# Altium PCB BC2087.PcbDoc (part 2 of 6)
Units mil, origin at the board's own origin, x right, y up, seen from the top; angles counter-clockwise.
Board outline 7401.57 x 1181.1 mil, 6 copper layers (Top Copper, Signal Layer 1, Signal Layer 2, Signal Layer 3, Signal Layer 4, Bottom Copper), stack 62.874 mil thick; 302 components, 237 nets, 1184 pads, 867 vias.
Unrouted connection lines stored in the file: 315.
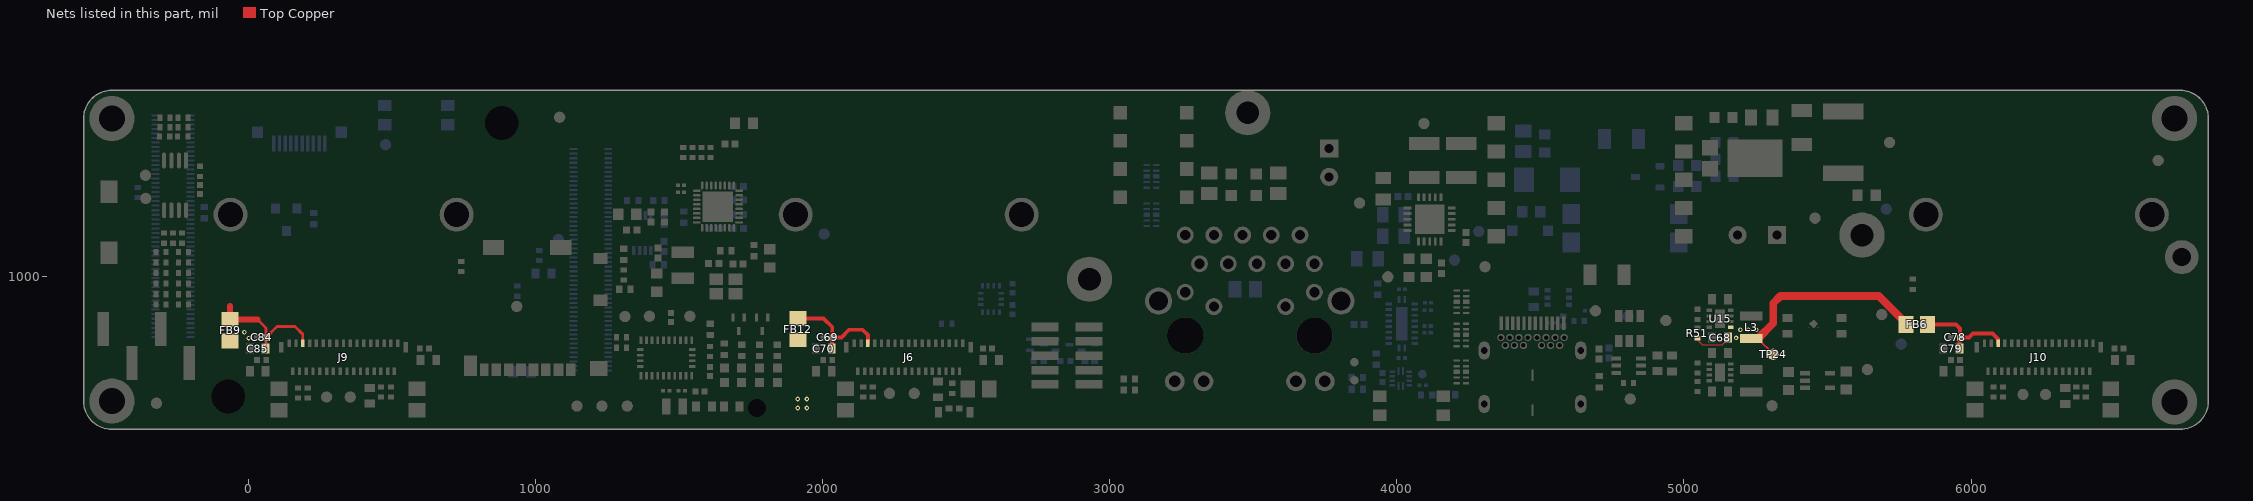
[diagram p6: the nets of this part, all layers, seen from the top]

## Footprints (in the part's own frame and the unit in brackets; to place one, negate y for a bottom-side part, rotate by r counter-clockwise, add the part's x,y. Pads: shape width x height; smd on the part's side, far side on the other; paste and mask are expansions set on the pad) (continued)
RESC0603(1608)_N [mm] "Chip Resistor, Body 1.6x0.8mm, IPC Medium Density"
  rect 0.9x1 smd: 1(-0.8,0) 2(0.8,0)
  silkscreen extent -0.05,-0.4 0.05,0.4, body extent -0.85,-0.47 0.85,0.47, height 0.6
RESC0805(2012)_N [mm] "Chip Resistor, Body 2.0x1.3mm, IPC Medium Density"
  rect 1.05x1.4 smd: 1(-0.95,0) 2(0.95,0)
  silkscreen extent -0.05,-0.6 0.05,0.6, body extent -1.1,-0.67 1.1,0.68, height 0.7
RESC1005X40X25NL05T05 [mm] "Chip Resistor, 2-Leads, Body 1.00x0.50mm, IPC Medium Density"
  rect 0.55x0.55 smd: 1(-0.45,0) 2(0.45,0)
  body extent -0.53,-0.27 0.53,0.28, height 0.4
RESC1005X40X25NL05T10 [mm] "Chip Resistor, 2-Leads, Body 1.00x0.50mm, IPC Medium Density"
  rect 0.6x0.55 smd: 1(-0.425,0) 2(0.425,0)
  body extent -0.53,-0.27 0.53,0.28, height 0.4
RS1B [mil] "Molded Diode, 2-Leads, Body 4.30x2.59mm, IPC Medium Density"
  rect 70x85 smd: 1(-80,0) 2(80,0)
  silkscreen extent -130,-59 91,59, body extent -102,-54 102,54, height 106
RTL8111Hx-CG [mm] "QFN, 32-Leads, Body 4.00x4.00mm, Pitch 0.40mm, Thermal Pad 2.70x2.70mm, IPC High Density"
  oval 0.7x0.2 smd mask+0.076: 1(-1.875,1.4) 2(-1.875,1) 3(-1.875,0.6) 4(-1.875,0.2) 5(-1.875,-0.2) 6(-1.875,-0.6) 7(-1.875,-1) 8(-1.875,-1.4) 17(1.875,-1.4) 18(1.875,-1) 19(1.875,-0.6) 20(1.875,-0.2) 21(1.875,0.2) 22(1.875,0.6) 23(1.875,1) 24(1.875,1.4)
  oval 0.2x0.7 smd mask+0.076: 9(-1.4,-1.875) 10(-1,-1.875) 11(-0.6,-1.875) 12(-0.2,-1.875) 13(0.2,-1.875) 14(0.6,-1.875) 15(1,-1.875) 16(1.4,-1.875) 25(1.4,1.875) 26(1,1.875) 27(0.6,1.875) 28(0.2,1.875) 29(-0.2,1.875) 30(-0.6,1.875) 31(-1,1.875) 32(-1.4,1.875)
  rect 2.7x2.7 smd paste-2 mask+0.076: 33(0,0)
  silkscreen extent -2.93,-2.15 2.15,2.15, body extent -2,-2 2,2, height 0.9
SFV10R-2STE1HLF [mm] "CONN FFC TOP 10POS 0.50MM R/A"
  rect 0.305x1.405 smd: 1(-2.258,0.494) 1(-2.258,0.494) 2(-1.759,0.494) 3(-1.258,0.494) 4(-0.758,0.494) 5(-0.258,0.494) 6(0.242,0.494) 7(0.741,0.494) 8(1.242,0.494) 9(1.742,0.494) 10(2.242,0.494)
  rect 1x1 smd: 11(-3.707,-0.486) 12(3.708,-0.494)
  Top Copper region: -3.958,0.394 -2.708,0.394 -2.708,-1.906 -3.958,-1.906
  Top Copper region: -5.358,-0.106 -2.708,-0.106 -2.708,-1.206 -5.358,-1.206
  Top Copper region: -4.658,0.394 -2.708,0.394 -2.708,-1.206 -4.658,-1.206
  Top Copper region: 4.642,-1.205 2.692,-1.205 2.692,0.395 4.642,0.395
  Top Copper region: 5.342,-1.205 2.692,-1.205 2.692,-0.105 5.342,-0.105
  Top Copper region: 3.942,-1.905 2.692,-1.905 2.692,0.395 3.942,0.395
  Keep-Out Layer region: 5.594,-5.708 5.594,-3.973 -5.611,-3.973 -5.611,-5.708
  body extent -5.26,-4.01 5.24,0.89, height 1.82
Si3404-A-GM [mm] "QFN, 20-Leads, Body 4.00x4.00mm, Pitch 0.50mm, Thermal Pad 2.60x2.60mm, IPC Medium Density"
  rect 0.7x0.25 smd: 1(-1.95,1) 2(-1.95,0.5) 3(-1.95,0) 4(-1.95,-0.5) 5(-1.95,-1) 11(1.95,-1) 12(1.95,-0.5) 13(1.95,0) 14(1.95,0.5) 15(1.95,1)
  rect 0.25x0.7 smd: 6(-1,-1.95) 7(-0.5,-1.95) 8(0,-1.95) 9(0.5,-1.95) 10(1,-1.95) 16(1,1.95) 17(0.5,1.95) 18(0,1.95) 19(-0.5,1.95) 20(-1,1.95)
  rect 2.6x2.6 smd paste-5: 21(0,0)
  silkscreen extent -2.82,-2.15 2.15,2.15, body extent -2,-2 2,2, height 0.9
SML_D1xx8W [mm] "Rohm LED SML_D1 series - Chip Diode, 2-Leads, Body 1.60x0.80mm, IPC High Density"
  rect 0.8x0.8 smd: 1(-0.625,0) 2(0.625,0)
  silkscreen extent -1.3,-0.5 -1.3,0.5, body extent -0.8,-0.4 0.8,0.4, height 0.6
TLV431BCDBZR [mm] "SOT-23-3"
  rrect18% 0.8x0.55 smd: 1(-1.1,0.95) 2(-1.1,-0.95) 3(1.1,0)
  silkscreen extent -1.23,-1.46 0.7,1.9, body extent -1.26,-1.46 1.26,1.46, height 0.96
TLV62080DSG [mm] "WSON-8, 2.1mm x 2.1mm x 0.8mm"
  rect 0.5x0.28 smd mask+0.07: 1(-0.95,0.75) 2(-0.95,0.25) 3(-0.95,-0.25) 4(-0.95,-0.75) 5(0.95,-0.75) 6(0.95,-0.25) 7(0.95,0.25) 8(0.95,0.75)
  rect 0.9x1.6 smd mask+0.07: 9(0,0)
  silkscreen extent -1.4,1.07 -1.35,1.13, body extent -1.05,-1.05 1.05,1.05, height 0.8
TLV70018DCK [mm] "SC70-5 1.1mm"
  rect 0.4x0.9 smd paste-0.025 mask+0.05: 1(-0.65,-1.1) 2(0,-1.1) 3(0.65,-1.1) 4(0.65,1.1) 5(-0.65,1.1)
  silkscreen extent -1.17,-1.63 -1.12,-1.57, body extent -1.1,-1.2 1.1,1.2, height 1.1
TP075_150_NS [mm] "0.75mm dia pad, 1.5mm dia clearance, no silk screen"
  round 0.75 smd paste-2: 1(0,0)
TP100_200_NS [mm] "1mm dia pad, 2mm dia clearance, no silk screen"
  round 1 smd paste-2: 1(0,0)
TPD4E02B04DQAR [mm] "TPD4E02B04DQAR"
  rrect50% 0.2x0.565 smd mask+0.07: 1(-1,-0.417) 2(-0.5,-0.417) 4(0.5,-0.417) 5(1,-0.417) 6(1,0.417) 7(0.5,0.417) 9(-0.5,0.417) 10(-1,0.417)
  rrect25% 0.4x0.565 smd mask+0.07: 3(0,-0.417) 8(0,0.417)
  silkscreen extent -1.4,-1.01 1.4,0.5, body extent -1.2,-0.71 1.2,0.71, height 0.55
TRJG0926HENL [mm] "TRXCOM TRJG0926HENL 1000BASE-T PoE"
  round 1.5 hole 0.9: 1(-5.715,8.89) 2(-4.445,6.35) 3(-3.175,8.89) 4(-1.905,6.35) 5(-0.635,8.89) 6(0.635,6.35) 7(1.905,8.89) 8(3.175,6.35) 9(4.445,8.89) 10(5.715,6.35) 11(-5.715,3.83) 12(-3.175,2.56) 13(3.175,2.56) 14(5.715,3.83)
  round 1.75 hole 1.02: 15(-6.63,-4.06) 16(-4.09,-4.06) 17(4.09,-4.06) 18(6.63,-4.06)
  round 2.4 hole 1.7: 19(8.064,3.05) 20(-8.064,3.05)
  round 3.2 hole 3.2: ""(-5.715,0) ""(5.715,0)
  silkscreen extent -8.11,-5 8.11,10.45, body extent -8.12,-10.8 8.12,10.45, height 13.65
TSOP-6-MFG [mm]
  rect 1.06x0.65 smd: 1(-1.1,0.95) 2(-1.1,0) 3(-1.1,-0.95) 4(1.1,-0.95) 5(1.1,0) 6(1.1,0.95)
  silkscreen extent -2.08,-1.5 0.2,1.5, body extent -1.73,-1.6 1.73,1.6, height 0.25
TXS0102DCUR [mm] "TSSOP, 8-Leads, Body 2.00x2.30mm, Pitch 0.50mm"
  rect 0.8x0.3 smd mask+0.05: 1(-1.55,0.75) 2(-1.55,0.25) 3(-1.55,-0.25) 4(-1.55,-0.75) 5(1.55,-0.75) 6(1.55,-0.25) 7(1.55,0.25) 8(1.55,0.75)
  silkscreen extent -1.78,-1.05 0.8,1.4, body extent -1.55,-1.05 1.55,1.05, height 0.9
VO618A-3X017T [mm] "4-SMD, Gull Wing"
  rect 1.52x1.78 smd: 1(-4.76,1.27) 2(-4.76,-1.27) 3(4.76,-1.27) 4(4.76,1.27)
  silkscreen extent -5.9,-2.29 2.8,2.7, body extent -5.08,-2.29 5.08,2.29, height 3.75
XDCR_BMI270 [mm]
  rect 0.475x0.25 smd: 1(-1.162,0.75) 2(-1.162,0.25) 3(-1.162,-0.25) 4(-1.162,-0.75) 8(1.162,-0.75) 9(1.162,-0.25) 10(1.162,0.25) 11(1.162,0.75)
  rect 0.25x0.475 smd: 5(-0.5,-0.913) 6(0,-0.913) 7(0.5,-0.913) 12(0.5,0.913) 13(0,0.913) 14(-0.5,0.913)
  silkscreen extent -2.07,-1.25 1.5,1.25, body extent -1.5,-1.25 1.5,1.25, height 0.87

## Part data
B1: library part DTSM-32N-V, "SWITCH TACTILE SMT 3.5mm * 6mm , brown 160gf", Manufacturer 1=Diptronics, Manufacturer Part Number 1=DTSM-32N-V-T/R, Max Operating Temperature=80°C, Min Operating Temperature=-30°C, Supplier Part Number 1=113-DTSM32NVTR
C1 C3: library part CL32B105KCJNNNE, "CAP CER 1UF 100V X7R 1210", Capacitance=1uF, Case Code (Imperial)=1210, Case Code (Metric)=3225, Dielectric=X7R, Manufacturer 1=Samsung, Max Operating Temperature=125°C, Min Operating Temperature=-55°C, Package Quantity=1, Supplier Part Number 1=1276-1812-1-ND, Tolerance=10%, Voltage Rating=100V
C2: library part EEU-FC2A120, "CAP ALUM 12UF 20% 100V RADIAL", Capacitance=12uF, Case/Package=Radial, ESR (Equivalent Series Resistance)=1.8R, Leakage Current=3uA, Manufacturer 1=Panasonic, Max Operating Temperature=105°C, Min Operating Temperature=-55°C, Package Quantity=200, Ripple Current=114mA, Supplier Part Number 1=P19496-ND, Tolerance=20%, Voltage=100V
C4 C8 C33 C50: library part CL21B104KCFNNNE, "CAP CER 0.1UF 100V X7R 0805", Capacitance=100nF, Case Code (Imperial)=0805, Case Code (Metric)=2012, Dielectric=X7R, Manufacturer 1=Samsung, Max Operating Temperature=125°C, Min Operating Temperature=-55°C, Supplier Part Number 1=1276-6840-1-ND, Tolerance=10%, Voltage Rating=100V
C5: library part GRM1885C1H102FA01D, "CAP CER 1000PF 50V C0G/NP0 0603", Capacitance=1nF, Case Code (Imperial)=0603, Case Code (Metric)=1608, Dielectric=C0G, Manufacturer=Murata, Max Operating Temperature=125°C, Min Operating Temperature=-55°C, Package Quantity=4000, Supplier Part Number 1=490-6376-1-ND, Temperature Coefficient=30ppm/°C, Tolerance=1%, Voltage=50V
C6: library part CL31A107MQHNNNE, "CAP CER 100UF 6.3V X5R 1206", Capacitance=100uF, Case Code (Imperial)=1206, Case Code (Metric)=3216, Dielectric=X5R, Manufacturer 1=Samsung, Max Operating Temperature=85°C, Min Operating Temperature=-55°C, Package Quantity=2000, Supplier Part Number 1=1276-1782-1-ND, Tolerance=20%, Voltage=6.3V
C7: library part ECA-0JM102, "CAP ALUM 1000UF 20% 6.3V RADIAL", Capacitance=1mF, Case/Package=Radial, Leakage Current=3uA, Manufacturer 1=Panasonic, Max Operating Temperature=85°C, Min Operating Temperature=-40°C, Package Quantity=200, Ripple Current=580mA, Supplier Part Number 1=P5115-ND, Tolerance=20%, Voltage=6.3V
C9: library part C0603C223K5RACTU, "CAP CER 0.022UF 50V X7R 0603", Capacitance=22nF, Case Code (Imperial)=0603, Case Code (Metric)=1608, Dielectric=X7R, Dielectric Material=Ceramic, Manufacturer 1=KEMET, Max Operating Temperature=125°C, Min Operating Temperature=-55°C, Package Quantity=4000, Supplier Part Number 1=399-1280-6-ND, Tolerance=10%, Voltage=50V
C10 C12 C34 C37 C40 C41 C42 C43 C44 C45 C52 C53 C69 C71 C75 C78 C80 C82 C84 C86 C88 C120: library part GRM155R71A104JA01D, "CAP CER 0.1UF 10V X7R 0402 5%", Capacitance=100nF, Case Code (Imperial)=0402, Case Code (Metric)=1005, Dielectric=X7R, Manufacturer 1=Murata, Max Operating Temperature=125°C, Min Operating Temperature=-55°C, Package Quantity=10000, Supplier Part Number 1=490-10777-1-ND, Tolerance=5%, Voltage Rating=10V
C11 C46 C47: library part GRM155R61E105KA12D, "CAP CER 1UF 25V X5R 0402 10%", Capacitance=1uF, Case Code (Imperial)=0402, Case Code (Metric)=1005, Dielectric=X5R, Manufacturer 1=Murata, Max Operating Temperature=85°C, Min Operating Temperature=-55°C, Package Quantity=10000, Supplier Part Number 1=490-10017-1-ND, Tolerance=10%, Voltage=25V
C13 C29: library part GRM033R60J105MEA2D, "CAP CER 1UF 6.3V X5R 0201 20%", Capacitance=1uF, Case Code (Imperial)=0201, Case Code (Metric)=0603, Dielectric=X5R, Manufacturer 1=Murata, Max Operating Temperature=85°C, Min Operating Temperature=-55°C, Package Quantity=1, Supplier Part Number 1=490-7229-1-ND, Tolerance=20%, Voltage=6.3V
C14 C59 C60 C65 C66 C67 C70 C72 C77 C79 C81 C83 C85 C87 C89: library part GRM188R61A106ME69D, "CAP CER 10UF 10V X5R 0603 20%", Capacitance=10uF, Case Code (Imperial)=0603, Case Code (Metric)=1608, Dielectric=X5R, Manufacturer 1=Murata, Max Operating Temperature=85°C, Min Operating Temperature=-55°C, Package Quantity=4000, Supplier Part Number 1=490-10475-1-ND, Tolerance=20%, Voltage Rating=10V
C15 C61 C62 C68: library part GRM188R61A226ME15D, "CAP CER 22UF 10V X5R 0603 20%", Capacitance=22uF, Case Code (Imperial)=0603, Case Code (Metric)=1608, Dielectric=X5R, Manufacturer 1=Murata, Max Operating Temperature=85°C, Min Operating Temperature=-55°C, Package Quantity=4000, Supplier Part Number 1=490-10476-1-ND, Tolerance=20%, Voltage Rating=10V
C16 C18: library part CMP-004-000018-2, "CAP CER 10UF 10V X5R 0603 20%", Case/Package=0603, Dielectric=X5R, Manufacturer 1=Murata, Max Operating Temperature=85°C, Min Operating Temperature=-55°C, Tolerance=20%, Voltage Rating=10V
C17 C19 C20: library part CMP-004-000013-2, "CAP CER 0.1UF 10V X7R 0402 5%", Case/Package=0402, Dielectric=X7R, Manufacturer 1=Murata, Max Operating Temperature=125°C, Min Operating Temperature=-55°C, Tolerance=5%, Voltage Rating=10V
C21 C36 C38 C39 C55: library part GRM188R61C475KAAJD, "CAP CER 4.7UF 16V X5R 0603 10%", Capacitance=4.7uF, Case Code (Imperial)=0603, Case Code (Metric)=1608, Dielectric=X5R, Manufacturer 1=Murata, Max Operating Temperature=85°C, Min Operating Temperature=-55°C, Package Quantity=4000, Supplier Part Number 1=490-10481-1-ND, Tolerance=10%, Voltage Rating=16V
C22: library part CL05B104KO5NFNC, "CAP CER 0.1UF 16V X7R 0402", Capacitance=100nF, Case Code (Imperial)=0402, Case Code (Metric)=1005, Dielectric=X7R, Manufacturer 1=Samsung, Max Operating Temperature=125°C, Min Operating Temperature=-55°C, Package Quantity=1, Supplier Part Number 1=1276-1508-1-ND, Tolerance=10%, Voltage Rating=16V
C23: library part GRM1885C1H222JA01D, "CAP CER 2200PF 50V C0G/NP0 0603", Capacitance=2.2nF, Case Code (Imperial)=0603, Case Code (Metric)=1608, Dielectric=C0G, Dielectric Material=Ceramic, Insulation Resistance=10GR, Manufacturer 1=Murata, Max Operating Temperature=125°C, Min Operating Temperature=-55°C, Package Quantity=1, Supplier Part Number 1=490-1459-1-ND, Temperature Coefficient=30ppm/°C, Tolerance=5%, Voltage=50V
C24: library part GRM155R71H103KA88D, "CAP CER 10000PF 50V X7R 0402", Capacitance=10nF, Case Code (Imperial)=0402, Case Code (Metric)=1005, Dielectric=X7R, Manufacturer 1=Murata, Max Operating Temperature=125°C, Min Operating Temperature=-55°C, Package Quantity=1, Supplier Part Number 1=490-4516-1-ND, Tolerance=10%, Voltage=25V, Voltage Rating=50V
C25 C26: library part C1206C102KGRACTU, "CAP CER 1000PF 2KV X7R 1206", Capacitance=1nF, Case/Package=1206, Dielectric=X7R, Dielectric Material=Ceramic, Manufacturer 1=KEMET, Max Operating Temperature=125°C, Min Operating Temperature=-55°C, Supplier Part Number 1=399-4819-1-ND, Tolerance=10%, Voltage Rating (DC)=2kV
C27 C28: library part CMP-004-000003-2, "Cap Ceramic 18pF 25V C0G 1% Pad SMD 0201 125C T/R", Case/Package=0201, Dielectric=C0G, Manufacturer 1=Murata, Max Operating Temperature=125°C, Min Operating Temperature=-55°C, Tolerance=1%, Voltage Rating=25V
C30 C35 C51 C58 C97 C208 C209 C211 C212: library part GRM033R61A104KE15D, "CAP CER 0.1UF 10V X5R 0201", Capacitance=100nF, Case Code (Imperial)=0201, Case Code (Metric)=0603, Dielectric=X5R, Manufacturer 1=Murata, Max Operating Temperature=85°C, Min Operating Temperature=-55°C, Package Quantity=1, Supplier Part Number 1=490-5881-1-ND, Tolerance=10%, Voltage=10V
C48 C49: library part C0402C270J5GACTU, "CAP CER 27PF 50V C0G/NP0 0402", Capacitance=27pF, Case Code (Imperial)=0402, Case Code (Metric)=1005, Dielectric=C0G, Dielectric Material=Ceramic, Manufacturer 1=KEMET, Max Operating Temperature=125°C, Min Operating Temperature=-55°C, Package Quantity=1, Supplier Part Number 1=399-1016-1-ND, Temperature Coefficient=30ppm/°C, Tolerance=5%, Voltage=50V
C73 C74 C76 C207: library part GRM155R60J106ME15D, "CAP CER 10UF 6.3V X5R 0402 20%", Capacitance=10uF, Case Code (Imperial)=0402, Case Code (Metric)=1005, Dielectric=X5R, Manufacturer 1=Murata, Max Operating Temperature=85°C, Min Operating Temperature=-55°C, Supplier Part Number 1=490-13238-1-ND, Tolerance=20%, Voltage Rating=6.3V
D1 D8: "CD-HD0x Series Schottky Bridge Rectifier Diode 100V 4-Pin Surface Mount T/R", Average Rectified Current=1A, Manufacturer 1=Bourns, Max Operating Temperature=125°C, Min Operating Temperature=-55°C, Supplier Part Number 1=CD-HD01CT-ND
D2: library part 1N4148W-7-F, "DIODE GEN PURP 100V 300MA SOD123", Average Rectified Current=300mA, Capacitance=2pF, Current=15A, Current Rating=150mA, Forward Voltage=1.25V, Manufacturer 1=Diodes, Max Forward Surge Current (Ifsm)=2A, Max Operating Temperature=150°C, Max Repetitive Reverse Voltage (Vrrm)=100V, Min Operating Temperature=-65°C, Package Quantity=3000, Peak Reverse Current=1uA, Power Dissipation=400mW, Supplier Part Number 1=1N4148W-FDICT-ND, Voltage Rating (DC)=75V
D3 D7: library part SML-D12D8WT86, "LED ORANGE DIFFUSED 0603 SMD Orange 605nm LED Indication - Discrete 2.2V 0603 (1608 Metric)", Case Code (Imperial)=0603, Case Code (Metric)=1608, Color=Orange, Forward Current=20mA, Forward Voltage=2.2V, Lens Color=White, Manufacturer 1=Rohm, Max Operating Temperature=85°C, Min Operating Temperature=-40°C, Package Quantity=1, Supplier Part Number 1=511-1577-1-ND
D4: "DIODE GEN PURP 100V 1A SMA", Average Rectified Current=1A, Capacitance=10pF, Case/Package=SMA, Forward Voltage=1.3V, Manufacturer 1="ON Semiconductor / Fairchild", Max Forward Surge Current (Ifsm)=30A, Max Operating Temperature=150°C, Max Repetitive Reverse Voltage (Vrrm)=100V, Min Operating Temperature=-55°C, Package Quantity=1, Peak Reverse Current=5uA, Power Dissipation=1.19W, Supplier Part Number 1=RS1BFSCT-ND
D5: library part PDS1040-13, "DIODE SCHOTTKY 40V 10A POWERDI5", Average Rectified Current=10A, Forward Voltage=510mV, Manufacturer 1=Diodes, Max Forward Surge Current (Ifsm)=275A, Max Operating Temperature=180°C, Max Repetitive Reverse Voltage (Vrrm)=40V, Min Operating Temperature=-65°C, Package Quantity=5000, Peak Reverse Current=700uA, Supplier Part Number 1=PDS1040DICT-ND
D6: library part SML-D12U8WT86, "LED RED DIFFUSED 0603 SMD Red 620nm LED Indication - Discrete 2.2V 0603 (1608 Metric)", Case Code (Imperial)=0603, Case Code (Metric)=1608, Color=Red, Forward Current=20mA, Forward Voltage=2.2V, Lens Color=White,Clear,Diffused, Manufacturer 1=Rohm, Max Operating Temperature=85°C, Min Operating Temperature=-40°C, Package Quantity=1, Supplier Part Number 1=511-1580-1-ND
D9 D10 D11: library part CMP-111-000006-1, "TVS DIODE 3.6V 8.8V 10USON 8.8V (Typ) Clamp 5A (8/20µs) Ipp Tvs Diode Surface Mount 10-USON (2.5x1)", Clamping Voltage=8.8V, Manufacturer 1="Texas Instruments", Max Operating Temperature=125°C, Min Breakdown Voltage=5.5V, Min Operating Temperature=-40°C, Operating Supply Voltage=3.6V, Peak Pulse Current=5A, Peak Pulse Power=17W, Power Line Protection=No
D12: library part CMP-007-00038-1, "Triple Color LED", Case/Package=1204, Colour=RGB, Forward Current=20mA, Manufacturer 1="Wurth Elektronik", Max Current Rating=30mA, Supplier Part Number 1=710-155124M173200
D16: library part SML-D12M8WT86, "LED GREEN DIFFUSED 0603 SMD Green 572nm LED Indication - Discrete 2.2V 0603 (1608 Metric)", Case Code (Imperial)=0603, Case Code (Metric)=1608, Color=Green,Yellow, Forward Current=20mA, Forward Voltage=2.2V, Illumination Color=Green, Lens Color=White,Diffused, Lens Colour=White,Clear,Diffused, Manufacturer=Rohm, Max Operating Temperature=85°C, Min Operating Temperature=-40°C, Package Quantity=1, Supplier Part Number 1=511-1578-1-ND
D17 D18: "TVS DIODE 3.6V 8.8V 10USON 8.8V (Typ) Clamp 5A (8/20µs) Ipp Tvs Diode Surface Mount 10-USON (2.5x1)", Clamping Voltage=8.8V, Manufacturer 1="Texas Instruments", Max Operating Temperature=125°C, Min Breakdown Voltage=5.5V, Min Operating Temperature=-40°C, Operating Supply Voltage=3.6V, Peak Pulse Current=5A, Peak Pulse Power=17W, Power Line Protection=No, Supplier Part Number 1=296-43875-1-ND
FB2 FB3: library part 742792040, "FERRITE BEAD 600 OHM 0805 1LN", Case Code (Imperial)=0805, Case Code (Metric)=2012, Case/Package=SMD/SMT, Current Rating=2A, DC Resistance (DCR)=150mR, Inductance=5.6H, Manufacturer 1="Wurth Electronics", Max Operating Temperature=125°C, Min Operating Temperature=-55°C, Package Quantity=1, Supplier Part Number 1=70996355, Test Frequency=100MHz, Tolerance=25%
FB4 FB5 FB6 FB7 FB8 FB9 FB10 FB11 FB12: library part 2508056017Y2, "FERRITE BEAD, 0.1OHM, 2A, 0805, 600R/100MHz", Case Code (Imperial)=0805, Case Code (Metric)=2012, Current Rating=2A, DC Resistance (DCR)=100mR, Frequency=100MHz, Manufacturer 1=Fair-Rite, Max Operating Temperature=125°C, Min Operating Temperature=-55°C, Package Quantity=4000, Resistance=350mR, Supplier Part Number 1=1934-1487-1-ND, Tolerance=25%
FID1 FID2 FID3 FID4 FID5 FID6: library part FIDUCIAL, "Fiducial with various available footprints"
J1: library part TRJG0926HENL, "CONN MAGJACK 1PORT 1000 BASET", Manufacturer 1=Trxcom
J2: library part CMP-005-000052-3, "OAK-SoM-Pro base board conn. A", Manufacturer 1=Hirose, Manufacturer Part Number 1=DF40HC(3.0)-100DS-0.4V(58), Package Quantity=1000
J3: library part CMP-005-000053-4, "OAK-SoM-Pro base board conn. B", Manufacturer 1=Hirose, Manufacturer Part Number 1=DF40HC(3.0)-100DS-0.4V(58), Package Quantity=1000
J4: library part SFV10R-2STE1HLF, "CONN FFC TOP 10POS 0.50MM R/A", Contact Resistance=30mR, Current Rating=500mA, Flammability Rating="UL94 V-0", Housing Color=Black, Insulation Resistance=100MR, Manufacturer 1="Amphenol FCI", Max Operating Temperature=105°C, Max Voltage Rating (AC)=50V, Min Operating Temperature=-55°C, Package Quantity=1, Supplier Part Number 1=609-4306-1-ND
J5: "CONN HEADER SMD 10POS 1.27MM", Color=Black, Contact Resistance=30mR, Manufacturer 1="Amphenol FCI", Max Operating Temperature=85°C, Max Voltage Rating (AC)=125V, Min Operating Temperature=-40°C, Package Quantity=93, Supplier Part Number 1=609-6529-ND
J6 J9 J10: library part AC_PY003-OV9282_CON, "FFC/FPC Connector, 33 Contact(s), 1 Row(s), Female, Right Angle, Surface Mount Terminal", Manufacturer 1=Hirose, Supplier Part Number 1=H125800CT-ND
J7: library part 104031-0811, "CONN MICRO SD CARD PUSH-PULL R/A", Manufacturer 1=Molex, Supplier Part Number 1=WM6357CT-ND
J8: library part CMP-002-00096-1, "USB C 3.1 Connector, 24 Contact(s), Female, Right Angle, Solder and Surface Mount Terminal, Receptacle", Manufacturer 1="Wurth Electronics", Supplier Part Number 1=732-9617-2-ND
L1: library part DO1608C-102ML, "IND POWER WIREWOUND 1uH 20% 100KHz FERRITE 2.7A", Case/Package=SMD/SMT, DC Resistance (DCR)=50mR, Inductance=1uH, Inductance Tolerance=20%, Manufacturer 1=Coilcraft, Manufacturer Part Number 1=DO1608C-102MLC, Max DC Current=2.7A, Max Operating Temperature=85°C, Min Operating Temperature=-40°C, Saturation Current=2.9A, Self Resonant Frequency=130MHz, Test Frequency=100kHz
L2: library part LQH32NH2R2J23L, "FIXED IND 2.2UH 610MA 97MOHM SMD", Case/Package=Nonstandard, Current Rating=610mA, DC Resistance (DCR)=97mR, Inductance=2.2uH, Manufacturer 1=Murata, Max Operating Temperature=125°C, Min Operating Temperature=-40°C, Ratings=AEC-Q200, Self Resonant Frequency=75MHz, Supplier Part Number 1=490-17367-1-ND, Test Frequency=1MHz, Tolerance=5%
L3 L4: library part DFE252012P-1R0M=P2, "FIXED IND 1UH 3.2A 42 MOHM SMD", Case Code (Imperial)=1008, Case Code (Metric)=2520, Current Rating=4.3A, DC Resistance (DCR)=42mR, Inductance=1uH, Manufacturer=Murata, Manufacturer Part Number=DFE252012P-1R0M{}P2, Max DC Current=3.2A, Max Operating Temperature=125°C, Min Operating Temperature=-40°C, Supplier Part Number 1=490-10647-1-ND, Test Frequency=1MHz, Tolerance=20%
MH1 MH2: library part 9774030243R, "MP ROUND STANDOFF M2X0.4 STEEL 3MM", Manufacturer 1="Wurth Electronics", Supplier Part Number 1=732-7085-1-ND
P1: library part CMP-002-00148-1, "Terminal and Terminal Block", Manufacturer 1="Wurth Elektronik", Max Operating Temperature=125°C, Min Operating Temperature=-40°C
Q1: library part DDTC114YCA-7-F, "TRANS PREBIAS NPN 200MW SOT23-3", Case/Package=SOT-23-3, Collector Emitter Breakdown Voltage=50V, Continuous Collector Current=100mA, Manufacturer 1=Diodes, Max Operating Temperature=150°C, Max Power Dissipation=200mW, Min Operating Temperature=-55°C, Package Quantity=3000, Supplier Part Number 1=DDTC114YCA-FDICT-ND, Transition Frequency=250MHz
Q2 Q3 Q4 Q5 Q6: "MOSFET N-CH 20V 0.2A EMT3", Case/Package=SOT-89, Continuous Drain Current (ID)=200mA, Drain to Source Voltage (Vdss)=20V, Input Capacitance=25pF, Manufacturer 1=Rohm, Max Power Dissipation=150mW, Supplier Part Number 1=RE1C002UNTCLCT-ND
Q7: library part CMP-016-000020-1, "MOSFET P-CH 20V 6.9A 6TSOP", Case/Package=TSOP, Continuous Drain Current (ID)=6.9A, Drain to Source Voltage (Vdss)=-20V, Gate to Source Voltage (Vgs)=12V, Input Capacitance=905pF, Manufacturer 1=Infineon, Max Operating Temperature=150°C, Max Power Dissipation=2W, Min Operating Temperature=-55°C, Threshold Voltage=-400mV
Q8: "Trench Power MOSFET, -20 V, -4.2 A, Single P-Channel, 6-Pin SC70, Pb-Free, Tape and Reel", Manufacturer 1="ON Semiconductor", Package Type="SC-88-6 / SC-70-6 / SOT-363-6"
R1 R2 R7 R9 R16 R19 R20 R21 R22 R23 R68 R81: library part CMP-013-000018-2, "RES SMD 10K OHM 1% 0402 1/16W Chip Resistor, 0402 [1005 Metric], 10 kohm, RC Series, 50 V, Thick Film, 62.5 mW", Case Code (Imperial)=0402, Case Code (Metric)=1005, Manufacturer 1=Yageo, Max Operating Temperature=155°C, Min Operating Temperature=-55°C, Power Rating=62.5mW, Resistance=10k, Temperature Coefficient=100ppm/°C, Tolerance=1%, Voltage Rating=50V
R3: library part CRCW060310R0FKEA, "RES SMD 10 OHM 1% 1/10W 0603", Case Code (Imperial)=0603, Case Code (Metric)=1608, Manufacturer 1=Vishay, Max Operating Temperature=155°C, Max Power Dissipation=100mW, Min Operating Temperature=-55°C, Package Quantity=10, Resistance=10R, Supplier Part Number 1=541-10.0HDKR-ND, Temperature Coefficient=100ppm/°C, Tolerance=1%, Voltage Rating=75V
R4: library part RC0603JR-0718KL, "RES SMD 18K OHM 5% 1/10W 0603", Case Code (Imperial)=0603, Case Code (Metric)=1608, Manufacturer 1=Yageo, Max Operating Temperature=155°C, Max Power Dissipation=100mW, Min Operating Temperature=-55°C, Package Quantity=1, Resistance=18kR, Supplier Part Number 1=311-18KGRCT-ND, Temperature Coefficient=100ppm/°C, Tolerance=5%, Voltage Rating=75V, Voltage Rating (DC)=50V
R5: library part RC0805FR-076R8L, "RES SMD 6.8 OHM 1% 1/8W 0805", Case Code (Imperial)=0805, Case Code (Metric)=2012, Manufacturer 1=Yageo, Max Operating Temperature=155°C, Max Power Dissipation=125mW, Min Operating Temperature=-55°C, Package Quantity=1, Resistance=6.8R, Supplier Part Number 1=311-6.80CRCT-ND, Temperature Coefficient=200ppm/°C, Tolerance=1%, Voltage Rating=150V
R6 R25: library part RC0402FR-0722RL, "RES SMD 22 OHM 1% 1/16W 0402", Case Code (Imperial)=0402, Case Code (Metric)=1005, Manufacturer 1=Yageo, Max Operating Temperature=155°C, Min Operating Temperature=-55°C, Power Rating=63mW, Resistance=22R, Supplier Part Number 1=311-22.0LRTR-ND, Temperature Coefficient=100ppm/°C, Tolerance=1%, Voltage Rating=50V
R8: library part CRCW080588K7FKEA, "RES SMD 88.7K OHM 1% 1/8W 0805", Case Code (Imperial)=0805, Case Code (Metric)=2012, Manufacturer 1=Vishay, Max Operating Temperature=155°C, Max Power Dissipation=125mW, Min Operating Temperature=-55°C, Package Quantity=10, Resistance=88.7kR, Supplier Part Number 1=541-88.7KCCT-ND, Temperature Coefficient=100ppm/°C, Tolerance=1%, Voltage Rating=150V
R10: library part RC0805FR-0748R7L, "RES SMD 48.7 OHM 1% 1/8W 0805", Case Code (Imperial)=0805, Case Code (Metric)=2012, Manufacturer 1=Yageo, Max Operating Temperature=155°C, Max Power Dissipation=125mW, Min Operating Temperature=-55°C, Package Quantity=1, Resistance=48.7R, Supplier Part Number 1=311-48.7CRCT-ND, Temperature Coefficient=100ppm/°C, Tolerance=1%, Voltage Rating=150V
R11: library part CRCW080524K3FKEA, "RES SMD 24.3K OHM 1% 1/8W 0805", Case Code (Imperial)=0805, Case Code (Metric)=2012, Manufacturer 1=Vishay, Max Operating Temperature=155°C, Max Power Dissipation=125mW, Min Operating Temperature=-55°C, Package Quantity=10, Resistance=24.3kR, Supplier Part Number 1=541-24.3KCCT-ND, Temperature Coefficient=100ppm/°C, Tolerance=1%, Voltage Rating=150V
R12: library part RC0603FR-074K99L, "RES SMD 4.99K OHM 1% 1/10W 0603", Case Code (Imperial)=0603, Case Code (Metric)=1608, Manufacturer 1=Yageo, Max Operating Temperature=155°C, Max Power Dissipation=100mW, Min Operating Temperature=-55°C, Package Quantity=1, Resistance=4.99kR, Supplier Part Number 1=311-4.99KHRCT-ND, Temperature Coefficient=100ppm/°C, Tolerance=1%, Voltage Rating=75V, Voltage Rating (DC)=50V
R13: library part RL0805FR-070R62L, "RES SMD 620 MOHM 1% 1/8W 0805", Case Code (Imperial)=0805, Case Code (Metric)=2012, Manufacturer 1=Yageo, Max Operating Temperature=125°C, Max Power Dissipation=125mW, Min Operating Temperature=-55°C, Package Quantity=1, Resistance=620mR, Supplier Part Number 1=311-.62SCT-ND, Temperature Coefficient=200ppm/°C, Tolerance=1%, Voltage Rating (DC)=300V
R14: library part RC0603FR-0736K5L, "RES SMD 36.5K OHM 1% 1/10W 0603", Case Code (Imperial)=0603, Case Code (Metric)=1608, Manufacturer 1=Yageo, Max Operating Temperature=155°C, Max Power Dissipation=100mW, Min Operating Temperature=-55°C, Package Quantity=1, Resistance=36.5kR, Supplier Part Number 1=311-36.5KHRCT-ND, Temperature Coefficient=100ppm/°C, Tolerance=1%, Voltage Rating=50V, Working Voltage=75V
R15: library part RC0603FR-0712K1L, "RES SMD 12.1K OHM 1% 1/10W 0603", Case Code (Imperial)=0603, Case Code (Metric)=1608, Manufacturer 1=Yageo, Max Operating Temperature=155°C, Max Power Dissipation=100mW, Min Operating Temperature=-55°C, Package Quantity=1, Resistance=12.1kR, Supplier Part Number 1=311-12.1KHRCT-ND, Temperature Coefficient=100ppm/°C, Tolerance=1%, Voltage Rating=50V
R17 R18 R38 R74 R75 R77: library part CRCW06030000Z0EA, "RES SMD 0 OHM JUMPER 1/10W 0603 0 Ohms Jumper 0.1W, 1/10W Chip Resistor 0603 (1608 Metric) Automotive AEC-Q200 Thick Film", Case Code (Imperial)=0603, Case Code (Metric)=1608, Current Rating=2A, Manufacturer 1=Vishay, Manufacturer Part Number 1=CRCW0603-0000Z0EA, Max Operating Temperature=155°C, Max Power Dissipation=100mW, Min Operating Temperature=-55°C, Package Quantity=1, Resistance=0mR, Supplier Part Number 1=541-0.0GCT-ND, Temperature Coefficient=100ppm/°C, Tolerance=5%, Voltage Rating=75V
R24: library part RC0603FR-072K05L, "RES SMD 2.05K OHM 1% 1/10W 0603", Case Code (Imperial)=0603, Case Code (Metric)=1608, Manufacturer 1=Yageo, Max Operating Temperature=155°C, Max Power Dissipation=100mW, Min Operating Temperature=-55°C, Package Quantity=1, Resistance=2.05kR, Supplier Part Number 1=311-2.05KHRCT-ND, Temperature Coefficient=100ppm/°C, Tolerance=1%, Voltage Rating=50V
R26 R30: library part RC0402FR-0749R9L, "RES SMD 49.9 OHM 1% 1/16W 0402", Case Code (Imperial)=0402, Case Code (Metric)=1005, Manufacturer 1=Yageo, Max Operating Temperature=155°C, Max Power Dissipation=63mW, Min Operating Temperature=-55°C, Package Quantity=1, Power Rating=62.5mW, Resistance=49.9R, Supplier Part Number 1=311-49.9LRCT-ND, Temperature Coefficient=100ppm/°C, Tolerance=1%, Voltage Rating=50V
R27 R66 R67: library part CRCW04020000Z0ED, "RES SMD 0 OHM JUMPER 1/16W 0402", Case Code (Imperial)=0402, Case Code (Metric)=1005, Manufacturer 1=Vishay, Max Operating Temperature=155°C, Max Power Dissipation=63mW, Min Operating Temperature=-55°C, Package Quantity=1, Resistance=0mR, Supplier Part Number 1=541-0.0JCT-ND, Temperature Coefficient=100ppm/°C, Tolerance=5%, Voltage Rating=50V
R28 R29 R35 R36 R37 R40 R41 R42 R43 R46 R49 R50 R54 R60 R61 R70 R71 R79 R128 R129 R130 R132 R133 R134 R135 R136 R183 R185 R186: library part RC0402FR-1310KL, "RES SMD 10K OHM 1% 0402 1/16W Chip Resistor, 0402 [1005 Metric], 10 kohm, RC Series, 50 V, Thick Film, 62.5 mW", Case Code (Imperial)=0402, Case Code (Metric)=1005, Manufacturer 1=Yageo, Max Operating Temperature=155°C, Min Operating Temperature=-55°C, Power Rating=62.5mW, Resistance=10kR, Supplier Part Number 1=67R9960, Temperature Coefficient=100ppm/°C, Tolerance=1%, Voltage Rating=50V
R31: library part CMP-115-000004-6, "RES SMD 10K OHM 1% 0402 1/16W Chip Resistor, 0402 [1005 Metric], 10 kohm, RC Series, 50 V, Thick Film, 62.5 mW", Case/Package=0402, Manufacturer 1=Yageo, Max Operating Temperature=155°C, Min Operating Temperature=-55°C, Power Rating=62.5mW, Temperature Coefficient=100ppm/°C, Tolerance=1%, Voltage Rating=50V
R32: library part CMP-115-000007-6, "RES SMD 0 OHM JUMPER 1/16W 0402", Case/Package=0402, Manufacturer 1=Vishay, Max Operating Temperature=155°C, Min Operating Temperature=-55°C, Power Rating=63mW, Temperature Coefficient=100ppm/°C, Tolerance=5%, Voltage Rating=50V
R33: library part RC0402FR-07300KL, "RES SMD 300K OHM 1% 1/16W 0402", Case Code (Imperial)=0402, Case Code (Metric)=1005, Manufacturer 1=Yageo, Max Operating Temperature=155°C, Min Operating Temperature=-55°C, Power Rating=63mW, Resistance=300kR, Supplier Part Number 1=311-300KLRCT-ND, Temperature Coefficient=100ppm/°C, Tolerance=1%, Voltage Rating=50V
R34: library part RC0402FR-0747KL, "RES SMD 47K OHM 1% 1/16W 0402", Case Code (Imperial)=0402, Case Code (Metric)=1005, Manufacturer 1=Yageo, Max Operating Temperature=155°C, Max Power Dissipation=63mW, Min Operating Temperature=-55°C, Package Quantity=1, Power Rating=62.5mW, Resistance=47kR, Supplier Part Number 1=311-47.0KLRCT-ND, Temperature Coefficient=100ppm/°C, Tolerance=1%, Voltage Rating=50V
R39: library part RC0603FR-0722RL, "RES SMD 22 OHM 1% 1/10W 0603", Case Code (Imperial)=0603, Case Code (Metric)=1608, Manufacturer 1=Yageo, Max Operating Temperature=155°C, Max Power Dissipation=100mW, Min Operating Temperature=-55°C, Package Quantity=1, Resistance=22R, Supplier Part Number 1=311-22.0HRCT-ND, Temperature Coefficient=100ppm/°C, Tolerance=1%, Voltage Rating=50V
R44 R45 R80 R82 R83: library part CMP-013-000022-2, "RES SMD 0 OHM JUMPER 1/16W 0402", Case Code (Imperial)=0402, Case Code (Metric)=1005, Manufacturer 1=Vishay, Max Operating Temperature=155°C, Max Power Dissipation=63mW, Min Operating Temperature=-55°C, Package Quantity=1, Resistance=0mR, Temperature Coefficient=100ppm/°C, Tolerance=5%, Voltage Rating=50V
R47: library part RC0402FR-071ML, "RES SMD 1M OHM 1% 1/16W 0402", Case Code (Imperial)=0402, Case Code (Metric)=1005, Manufacturer 1=Yageo, Max Operating Temperature=155°C, Min Operating Temperature=-55°C, Power Rating=63mW, Resistance=1MR, Supplier Part Number 1=311-1.00MLRCT-ND, Temperature Coefficient=100ppm/°C, Tolerance=1%, Voltage Rating=50V
R48: library part RC0402FR-072K49L, "RES SMD 2.49K OHM 1% 1/16W 0402", Case Code (Imperial)=0402, Case Code (Metric)=1005, Manufacturer 1=Yageo, Max Operating Temperature=155°C, Max Power Dissipation=63mW, Min Operating Temperature=-55°C, Package Quantity=1, Power Rating=62.5mW, Resistance=2.49kR, Supplier Part Number 1=311-2.49KLRCT-ND, Temperature Coefficient=100ppm/°C, Tolerance=1%, Voltage Rating=50V
R51: library part CRCW040253K6FKED, "RES SMD 53.6K OHM 1% 1/16W 0402", Case Code (Imperial)=0402, Case Code (Metric)=1005, Manufacturer 1=Vishay, Max Operating Temperature=155°C, Max Power Dissipation=63mW, Min Operating Temperature=-55°C, Package Quantity=10, Resistance=53.6kR, Supplier Part Number 1=541-53.6KLCT-ND, Temperature Coefficient=100ppm/°C, Tolerance=1%, Voltage Rating=50V
R52: library part CRCW040239K2FKED, "RES SMD 39.2K OHM 1% 1/16W 0402", Case Code (Imperial)=0402, Case Code (Metric)=1005, Manufacturer 1=Vishay, Max Operating Temperature=155°C, Max Power Dissipation=63mW, Min Operating Temperature=-55°C, Package Quantity=10, Resistance=39.2kR, Supplier Part Number 1=541-39.2KLCT-ND, Temperature Coefficient=100ppm/°C, Tolerance=1%, Voltage Rating=50V
R53 R55 R56 R62: library part RC0402FR-071KL, "RES SMD 1K OHM 1% 1/16W 0402 1 kOhms ±1% 0.063W, 1/16W Chip Resistor 0402 (1005 Metric) Moisture Resistant Thick Film", Case Code (Imperial)=0402, Case Code (Metric)=1005, Manufacturer 1=Yageo, Max Operating Temperature=155°C, Min Operating Temperature=-55°C, Power Rating=62.5mW, Resistance=1kR, Supplier Part Number 1=311-1.00KLRCT-ND, Temperature Coefficient=100ppm/°C, Tolerance=1%, Voltage Rating=50V
R57 R58 R59 R76: library part CRCW0402470RFKED, "RES SMD 470 OHM 1% 1/16W 0402", Case Code (Imperial)=0402, Case Code (Metric)=1005, Manufacturer 1=Vishay, Max Operating Temperature=155°C, Max Power Dissipation=63mW, Min Operating Temperature=-55°C, Package Quantity=10, Resistance=470R, Supplier Part Number 1=541-470LCT-ND, Temperature Coefficient=100ppm/°C, Tolerance=1%, Voltage Rating=50V
R63: library part CMP-009-00197-1, "Fixed Resistor, Metal Glaze/thick Film, 0.1W, 750ohm, 50V, 1% +/-Tol, 100ppm/Cel, Surface Mount, 0402", Case/Package=0402, Manufacturer 1=Panasonic, Power=100mW, Supplier Part Number 1=P750LTR-ND, Tolerance=1%
R64: library part CMP-009-00198-1, "Fixed Resistor, Metal Glaze/thick Film, 0.063W, 1200ohm, 50V, 1% +/-Tol, 100ppm/Cel, Surface Mount, 0402", Case/Package=0402, Manufacturer 1=Vishay, Power=63mW, Supplier Part Number 1=541-1.20KLTR-ND, Tolerance=1%, Voltage Rating=50V
R65: library part CMP-009-00196-1, "Fixed Resistor, Metal Glaze/thick Film, 0.0625W, 150ohm, 50V, 1% +/-Tol, 100ppm/Cel, Surface Mount, 0402", Manufacturer 1=Yageo, Tolerance=1%, Voltage Rating=50V
R69: library part RC0402FR-07100KL, "RES SMD 100K OHM 1% 1/16W 0402", Case Code (Imperial)=0402, Case Code (Metric)=1005, Manufacturer 1=Yageo, Max Operating Temperature=155°C, Max Power Dissipation=63mW, Min Operating Temperature=-55°C, Package Quantity=1, Resistance=100kR, Supplier Part Number 1=311-100KLRCT-ND, Temperature Coefficient=100ppm/°C, Tolerance=1%, Voltage Rating=50V
R72 R73: library part CMP-013-000013-8, "RES SMD 2.2K OHM 1% 1/16W 0402", Case/Package=0402, Manufacturer 1=Yageo, Max Operating Temperature=155°C, Min Operating Temperature=-55°C, Power Rating=63mW, Tolerance=1%, Voltage Rating=50V
R78: library part ERJ-2RKF1782X, "RES SMD 17.8K OHM 1% 1/10W 0402 17.8 kOhms ±1% 0.1W, 1/10W Chip Resistor 0402 (1005 Metric) Automotive AEC-Q200 Thick Film", Case Code (Imperial)=0402, Case Code (Metric)=1005, Manufacturer 1=Panasonic, Max Operating Temperature=155°C, Max Power Dissipation=100mW, Min Operating Temperature=-55°C, Package Quantity=1, Resistance=17.8kR, Supplier Part Number 1=P17.8KLCT-ND, Temperature Coefficient=100ppm/°C, Tolerance=1%, Voltage Rating=50V
R131: library part RC0402FR-071KL, "RES SMD 1K OHM 1% 1/16W 0402", Case Code (Imperial)=0402, Case Code (Metric)=1005, Manufacturer 1=Yageo, Max Operating Temperature=155°C, Min Operating Temperature=-55°C, Power Rating=62.5mW, Resistance=1kR, Supplier Part Number 1=311-1.00KLRCT-ND, Temperature Coefficient=100ppm/°C, Tolerance=1%, Voltage Rating=50V
R187 R190: library part CRCW04021M80FKED, "RES SMD 1.8M OHM 1% 1/16W 0402", Case Code (Imperial)=0402, Case Code (Metric)=1005, Manufacturer 1=Vishay, Max Operating Temperature=155°C, Min Operating Temperature=-55°C, Package Quantity=10000, Power Rating=63mW, Resistance=1.8MR, Supplier Part Number 1=541-1.80MLCT-ND, Temperature Coefficient=100ppm/°C, Tolerance=1%, Voltage Rating=50V
R213 R214: library part CMP-115-000004-1, "RES SMD 10K OHM 1% 0402 1/16W Chip Resistor, 0402 [1005 Metric], 10 kohm, RC Series, 50 V, Thick Film, 62.5 mW", Case Code (Imperial)=0402, Case Code (Metric)=1005, Manufacturer 1=Yageo, Max Operating Temperature=155°C, Min Operating Temperature=-55°C, Power Rating=62.5mW, Resistance=10kR, Temperature Coefficient=100ppm/°C, Tolerance=1%, Voltage Rating=50V
SW1 SW2: library part CMP-011-00016-3, "Keypad Switch, 1 Switches, SPST, Momentary-tactile, 0.05A, 12VDC, 2.65N, Solder Terminal, Surface Mount-right Angle", Current Rating=50mA, Manufacturer 1="Wurth Electronics", Supplier Part Number 1=732-7055-2-ND, Voltage Rating=12V
T1: "TRANS FLYBACK POE 127UH SMD", Case/Package=SMD/SMT, Current Rating=1.3A, Frequency=500kHz, Inductance=127uH, Manufacturer 1="Wurth Electronics", Max Input Voltage=57V, Max Operating Temperature=125°C, Min Input Voltage=36V, Min Operating Temperature=-40°C, Output Voltage=5V, Package Quantity=1, Power Rating=13W, Supplier Part Number 1=732-2432-1-ND
TP1 TP2 TP3 TP4 TP5 TP6 TP7 TP8 TP9 TP10 TP11 TP12 TP13 TP14 TP15 TP16 TP17 TP18 TP19 TP20 TP22 TP23 TP24 TP27 TP28 TP29 TP30 TP31 TP32 TP33: library part TEST_POINT
TP21 TP25 TP26 TP34 TP35 TP41: library part CMP-015-000000-1
U1: "IC POE CNTRL 1 CHANNEL 20QFN", Manufacturer 1="Silicon Labs", Supplier Part Number 1=336-4270-ND
U2: "OPTOISOLATOR 5.3KV TRANS 4-SMD", Case/Package=SMD/SMT, Collector Emitter Saturation Voltage=400mV, Collector Emitter Voltage (VCEO)=80V, Current Transfer Ratio=100%, Forward Current=60mA, Forward Voltage=1.1V, Isolation Voltage=5.3kV, Manufacturer 1="Vishay Semiconductors", Max Collector Current=50mA, Max Operating Temperature=110°C, Max Power Dissipation=150mW, Min Operating Temperature=-55°C, Package Quantity=1, Reverse Breakdown Voltage=6V, Supplier Part Number 1=VO618A-3X017TCT-ND
U3 U15: "IC REG BUCK ADJ 1.2A SYNC 8WSON", Manufacturer 1="Texas Instruments", Manufacturer Part Number 1=TLV62080DSGR, Manufacturer Part Number 2=TLV62080DSGT, Max Input Voltage=5.5V, Max Operating Temperature=125°C, Max Output Current=1.2A, Max Output Voltage=4V, Min Input Voltage=2.5V, Min Operating Temperature=-40°C, Min Output Voltage=500mV, Nominal Supply Current=30uA, Package Quantity=3000, Supplier Part Number 1=296-39270-1-ND, Switching Frequency=2MHz
U4: library part RTL8111HS, "IC ETHERNET/PCIe PHY Realtek", Manufacturer 1=Realtek
U5: library part TLV431BCDBZR, "IC VREF SHUNT ADJ SOT23-3", Case/Package=SOT-23, Cathode Current=100uA, Manufacturer 1="Texas Instruments", Max Input Voltage=7V, Max Operating Temperature=125°C, Max Output Current=15mA, Max Output Voltage=6V, Min Input Voltage=1.24V, Min Operating Temperature=-40°C, Package Quantity=1, Supplier Part Number 1=296-17569-1-ND, Temperature Coefficient=129ppm/°C, Tolerance=0.5%
U6: library part TXS0102DCUR, "TEXAS INSTRUMENTS - TXS0102DCUR - IC, TRANSLATOR, 2 BIT, BI, US-8", Case/Package=VSSOP, High Level Output Current=-20uA, Low Level Output Current=1mA, Manufacturer 1="Texas Instruments", Max Operating Temperature=85°C, Max Supply Voltage=5.5V, Min Operating Temperature=-40°C, Min Supply Voltage=1.65V, Nominal Supply Current=14.4uA, Output Current=1A, Package Quantity=1, Supplier Part Number 1=296-21931-1-ND
U7: library part 24AA32A-I/MS, "IC EEPROM 32K I2C 400KHZ 8MSOP Memory IC 32Kb (4K x 8) I²C 400kHz 900ns 8-MSOP", Case/Package=MSOP, Frequency=400kHz, Manufacturer 1=Microchip, Max Operating Temperature=85°C, Max Supply Voltage=5.5V, Min Operating Temperature=-40°C, Min Supply Voltage=1.7V, Nominal Supply Current=3mA, Package Quantity=100, Supplier Part Number 1=24AA32A-I/MS-ND
U8: library part CMP-099-000001-1, "IC OR CTRLR IDEAL DIODE SC70-6", Manufacturer 1="Texas Instruments"
U9: "Accelerometer, Gyroscope, 6 Axis Sensor IÂ²C, SPI Output", Manufacturer 1="Bosch Sensortec", Package="LGA-14 Bosch Sensortec"
U10: "IC REG LINEAR 1.8V 200MA SC70-5 Linear Voltage Regulator IC  1 Output  200mA SC-70-5", Case/Package=SC, Dropout Voltage=175mV, Manufacturer 1="Texas Instruments", Manufacturer Part Number 1=TLV70018DCKR, Manufacturer Part Number 2=TLV70018DCKT, Max Input Voltage=5.5V, Max Operating Temperature=125°C, Max Output Current=200mA, Max Output Voltage=1.8V, Max Power Dissipation=320mW, Min Current Limit=220mA, Min Input Voltage=2V, Min Operating Temperature=-40°C, Nominal Supply Current=31uA, Output Voltage Accuracy=2%, Package Quantity=1, Quiescent Current=30uA, Supplier Part Number 1=296-32409-1-ND
U11: library part CMP-016-000000-1, "IMU ACCEL/GYRO/MAG I2C 32BIT", Case/Package=LGA, Manufacturer 1="Hillcrest Laboratories", Max Operating Temperature=85°C, Min Operating Temperature=-40°C
U14: library part CMP-019-00053-2, "Fixed Positive LDO Regulator, 2.8V, 0.23V Dropout, CMOS, PDSO4", Case/Package=UDFN-4, Dropout Voltage=155mV, Manufacturer 1=OnSemi, Max Supply Voltage=5.5V, Min Supply Voltage=1.7V, Output Current=300mA, Output Voltage=2.8V, Supplier Part Number 1=863-NCP114AMX280TCG
U61: library part CMP-045-000000-1, "Multiplexer And Demux/Decoder, CBT/FST/QS/5C/B Series, 1-Func, 2 Line Input, 1 Line Output, True Output, PQCC20", Manufacturer 1="NXP Semiconductors", Manufacturer Part Number 1=CBTL02043ABQ,115
U62: library part CMP-044-000000-2, "Power Supply Support Circuit, Fixed, 2 Channel, 0.2, PQCC12", Manufacturer 1="NXP Semiconductors", Manufacturer Part Number 1=PTN5150HXMP
X1: library part ECS-250-18-36B-CKY-TR, "CRYSTAL 25.0000MHZ 18PF SMD 25MHz ±10ppm Crystal 18pF 50 Ohms 4-SMD, No Lead", Manufacturer 1="ECS International", Supplier Part Number 1=XC3051CT-ND
Y1: library part CMP-006-000001-2, "CRYSTAL 32.768kHz ±20ppm Crystal 12.5pF 90 kOhms 2-SMD, No Lead", Case/Package=SMD/SMT, Frequency=32.768kHz, Manufacturer 1=Abracon, Max Operating Temperature=85°C, Min Operating Temperature=-40°C, Tolerance=20ppm

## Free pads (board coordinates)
  round 157.48 / inner round 98.43 / far side round 157.48 hole 90.55: 2(-476.23,567.36) 2(-476.23,1551.61) 2(6708.81,564.45) 2(6708.81,1551.61)
  round 0 hole 62.99 unplated: 2(1771.65,543.31)
  round 157.48 / inner round 98.43 / far side round 157.48 hole 78.74: 2(2929.28,992.13) 2(3480.31,1571.85) 2(5620.2,1145.67)
  round 118.11 / inner round 78.74 / far side round 118.11 hole 62.99: 2(6734,1069)
  round 118.11 hole 86.61: 3(-62.85,1216.96) 3(724.55,1216.96) 3(1905.66,1216.96) 3(2693.06,1216.96) 3(5842.66,1216.96) 3(6630.07,1216.96)

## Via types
v1: diameter 20, hole 10, Top Copper to Bottom Copper, 273 vias
v2: diameter 16, hole 8, Top Copper to Bottom Copper, tented both sides, 243 vias
v3: diameter 15.98, hole 7.99, Top Copper to Bottom Copper, tented both sides, 201 vias
v4: diameter 18, hole 8, Top Copper to Bottom Copper, tented both sides, 70 vias
v5: diameter 16, hole 7.95, Top Copper to Bottom Copper, tented both sides, 36 vias
v6: diameter 20, hole 10, Top Copper to Bottom Copper, tented both sides, 26 vias
v7: diameter 16, hole 8, Top Copper to Bottom Copper, 17 vias
v8: diameter 19.68, hole 11.81, Top Copper to Bottom Copper, tented both sides, 1 vias

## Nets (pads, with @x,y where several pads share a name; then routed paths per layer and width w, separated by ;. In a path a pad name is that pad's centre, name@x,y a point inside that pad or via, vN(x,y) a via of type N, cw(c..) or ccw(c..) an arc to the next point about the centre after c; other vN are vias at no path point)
1V2: C68.2 FB6.1 FB9.1 FB12.1 L3.2 R51.2 TP24.1 U15.5 | length 894.6
  Top Copper w4: R51.2@5047.24,786.73 5047.24,780.53 5063.99,763.78 5134.14,763.78 5153.54,783.18 C68.2@5153.54,788.7
  Top Copper w4.53: L3.2@5234.25,785.43 5257.87,785.43 5311.02,732.28 TP24.1@5311.02,730.62
  Top Copper w27.56: L3.2@5257.87,785.43 5311.02,838.58 5311.02,908.32 5336.15,933.45 5678.76,933.45 5773.62,838.58 FB6.1@5773.62,834.65
  other v2: 5181.59,787.4 5196.85,816.23 5224.41,816.23 5251.97,816.23
  other v3: 1913.39,543.31 1944.88,543.31 1913.39,574.8 1944.88,574.8 1,787 -14.42,807
1V2_CAM_M: C69.2 C70.2 FB12.2 J6.29 | length 379.6
  Top Copper w13.78: FB12.2@1913.44,855.74 2002.2,855.74 2033.16,824.78 C69.2@2033.16,789.59 ; C70.2@2031.6,750.22 2032.38,751 2032.38,788.81 C69.2@2033.16,789.59 ; J6.29@2157.33,768.34 2157.33,797.39 2138.78,815.94 2091.54,815.94 2065.18,789.59 C69.2@2033.16,789.59
1V2_L: C78.2 C79.2 FB6.2 J10.29 | length 367
  Top Copper w4.02: J10.29@6094.34,768.34 6094.34,783.61
  Top Copper w13.78: FB6.2@5848.43,834.65 5947.16,834.65 5961.31,820.49 C78.2@5961.31,789.59 ; C79.2@5959.74,750.22 5960.52,751.01 5960.52,788.8 C78.2@5961.31,789.59 ; J10.29@6094.34,768.34 6094.34,783.61 6074.8,803.15 6007.26,803.15 5993.7,789.59 C78.2@5961.31,789.59
1V2_R: C84.2 C85.2 FB9.2 J9.29 | length 443.4
  Top Copper w10: 31.3,851.67 60.74,822.23 60.74,790.29 C84.2@61.44,789.59 ; C85.2@59.47,750.22 60.45,751.2 60.45,788.6 C84.2@61.44,789.59 ; J9.29@188.83,768.34 188.83,800.39 162.22,827 98.85,827 C84.2@61.44,789.59
  Top Copper w20: FB9.2@-64.47,851.67 31.3,851.67
  Top Copper w22: FB9.2@-64.47,851.67 -64.47,898.63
